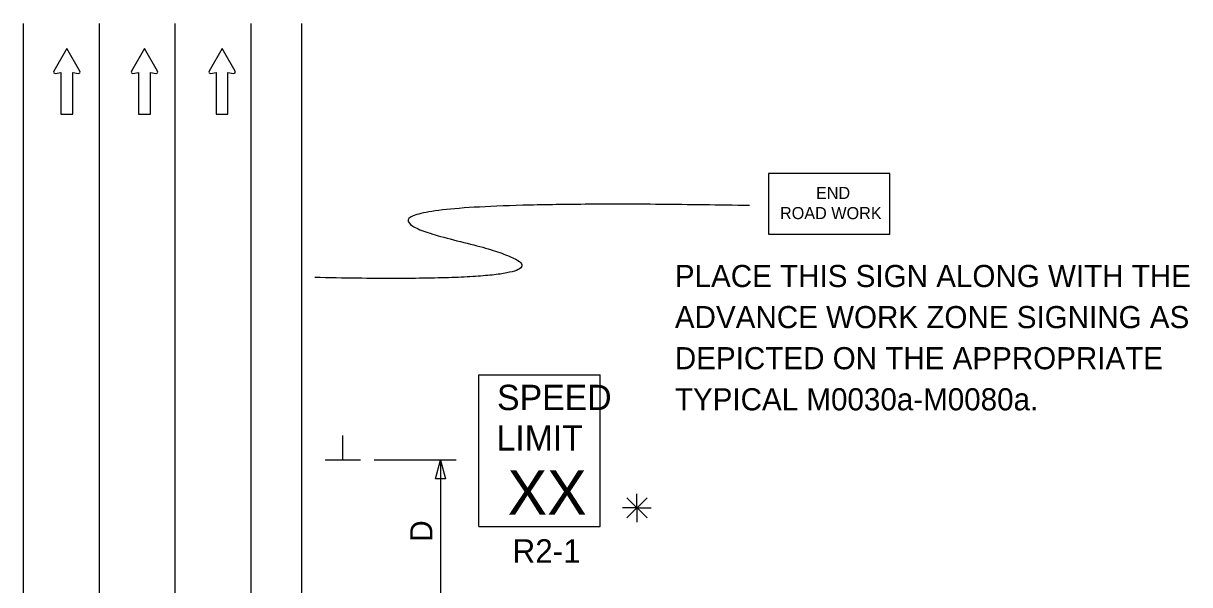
# Model space of a CAD drawing. Extents: x 16744 to 19504, y 5731 to 6974.
# Drawn here: x 17973.5 to 18342.6, y 6713.6 to 6891.2 of the extents above; entities that cross this region are included whole.
import ezdxf

# ---------------------------------------------------------------- set-up
doc = ezdxf.new("R2010")
doc.units = 0
for name, color, linetype in [('ALI_LEGAL_EX', 7, 'Continuous'), ('MT_SCRATCH_LEVEL_E', 7, 'Continuous'), ('PAVT_EDGE_EX', 7, 'Continuous'), ('TRAFFIC_SIGNS_PR', 7, 'Continuous'), ('TYPICAL_TEXT_DIMEN_PR', 7, 'Continuous')]:
    doc.layers.add(name, color=color, linetype=linetype)

msp = doc.modelspace()

# ---------------------------------------------------------------- linework, layer by layer
at = {"layer": 'ALI_LEGAL_EX'}
for p, q in [((17997.5, 6891.16), (17997.5, 6061.98)), ((18021.5, 6891.16), (18021.5, 6061.98)), ((18021.5, 6891.16), (18021.5, 6061.98))]:
    msp.add_line(p, q, dxfattribs=at)
for points in [[(17997.5, 6891.16), (17997.5, 6866.16)], [(18021.5, 6891.16), (18021.5, 6866.16)], [(17997.5, 6791.16), (17997.5, 6766.16)], [(18021.5, 6791.16), (18021.5, 6766.16)]]:
    msp.add_lwpolyline(points, dxfattribs=at)
at = {"layer": 'MT_SCRATCH_LEVEL_E'}
for p, q in [((17987.26, 6883.24), (17983.15, 6876)), ((17987.26, 6883.24), (17983.15, 6876)), ((17991.41, 6876), (17987.26, 6883.24)), ((17991.41, 6876), (17987.26, 6883.24)), ((18011.82, 6883.24), (18007.71, 6876)), ((18011.82, 6883.24), (18007.71, 6876)), ((18015.97, 6876), (18011.82, 6883.24)), ((18015.97, 6876), (18011.82, 6883.24)), ((18036.38, 6883.24), (18032.27, 6876)), ((18036.38, 6883.24), (18032.27, 6876)), ((18040.53, 6876), (18036.38, 6883.24)), ((18040.53, 6876), (18036.38, 6883.24)), ((17983.64, 6875.32), (17985.41, 6875.64)), ((17983.64, 6875.32), (17985.41, 6875.64)), ((17985.41, 6875.64), (17985.41, 6862.38)), ((17985.41, 6875.64), (17985.41, 6862.38)), ((17989.15, 6862.38), (17989.15, 6875.64)), ((17989.15, 6875.64), (17990.93, 6875.32)), ((17989.15, 6862.38), (17989.15, 6875.64)), ((17989.15, 6875.64), (17990.93, 6875.32)), ((18008.19, 6875.32), (18009.97, 6875.64)), ((18008.19, 6875.32), (18009.97, 6875.64)), ((18009.97, 6875.64), (18009.97, 6862.38)), ((18009.97, 6875.64), (18009.97, 6862.38)), ((18013.71, 6862.38), (18013.71, 6875.64)), ((18013.71, 6875.64), (18015.49, 6875.32)), ((18013.71, 6862.38), (18013.71, 6875.64)), ((18013.71, 6875.64), (18015.49, 6875.32)), ((18032.75, 6875.32), (18034.53, 6875.64)), ((18032.75, 6875.32), (18034.53, 6875.64)), ((18034.53, 6875.64), (18034.53, 6862.38)), ((18034.53, 6875.64), (18034.53, 6862.38)), ((18038.27, 6862.38), (18038.27, 6875.64)), ((18038.27, 6875.64), (18040.05, 6875.32)), ((18038.27, 6862.38), (18038.27, 6875.64)), ((18038.27, 6875.64), (18040.05, 6875.32)), ((17985.41, 6862.38), (17989.15, 6862.38)), ((17985.41, 6862.38), (17989.15, 6862.38)), ((18009.97, 6862.38), (18013.71, 6862.38)), ((18009.97, 6862.38), (18013.71, 6862.38)), ((18034.53, 6862.38), (18038.27, 6862.38)), ((18034.53, 6862.38), (18038.27, 6862.38))]:
    msp.add_line(p, q, dxfattribs=at)
for centre, start, end in [((17983.56, 6875.78), 150.4248, 279.9638), ((17983.56, 6875.78), 150.4248, 279.9638), ((17991, 6875.78), 260.0362, 29.7731), ((17991, 6875.78), 260.0362, 29.7731), ((18008.12, 6875.78), 150.4248, 279.9638), ((18008.12, 6875.78), 150.4248, 279.9638), ((18015.56, 6875.78), 260.0362, 29.7731), ((18015.56, 6875.78), 260.0362, 29.7731), ((18032.68, 6875.78), 150.4248, 279.9638), ((18032.68, 6875.78), 150.4248, 279.9638), ((18040.12, 6875.78), 260.0362, 29.7731), ((18040.12, 6875.78), 260.0362, 29.7731)]:
    msp.add_arc(centre, 0.463, start, end, dxfattribs=at)
at = {"layer": 'PAVT_EDGE_EX'}
for p, q in [((17973.5, 6891.16), (17973.5, 6061.98)), ((17973.5, 6891.16), (17973.5, 6061.98)), ((18045.5, 6891.16), (18045.5, 6061.98)), ((18061.5, 6891.16), (18061.5, 6061.98))]:
    msp.add_line(p, q, dxfattribs=at)
at = {"layer": 'TRAFFIC_SIGNS_PR'}
for p, q in [((18117.64, 6779.97), (18156.04, 6779.97)), ((18117.64, 6731.97), (18117.64, 6779.97)), ((18156.04, 6731.97), (18156.04, 6779.97)), ((18117.64, 6731.97), (18156.04, 6731.97))]:
    msp.add_line(p, q, dxfattribs=at)
msp.add_lwpolyline([(18209.35, 6824.48), (18247.75, 6824.48), (18247.75, 6843.68), (18209.35, 6843.68)], close=True, dxfattribs=at)
msp.add_open_spline([(18203.28, 6833.52), (18053.97, 6836.16), (18167.87, 6808.58), (18065.7, 6810.75)], degree=2, dxfattribs=at)
at = {"layer": 'TYPICAL_TEXT_DIMEN_PR'}
for p, q in [((18074.63, 6752.97), (18074.63, 6760.76)), ((18080.25, 6752.97), (18069, 6752.97)), ((18110.5, 6752.97), (18084.5, 6752.97)), ((18103.93, 6747.11), (18105.5, 6752.97)), ((18105.5, 6752.97), (18105.5, 6702.97)), ((18105.5, 6752.97), (18107.07, 6747.11)), ((18105.5, 6747.11), (18103.93, 6747.11)), ((18107.07, 6747.11), (18105.5, 6747.11)), ((18170.87, 6741.1), (18164.49, 6734.73)), ((18164.5, 6741.1), (18170.87, 6734.73)), ((18167.68, 6737.91), (18167.68, 6742.37)), ((18167.68, 6737.91), (18163.15, 6737.91)), ((18167.68, 6737.91), (18170.87, 6737.91)), ((18167.68, 6737.91), (18172.16, 6737.91)), ((18167.68, 6737.91), (18167.68, 6733.41))]:
    msp.add_line(p, q, dxfattribs=at)

# ---------------------------------------------------------------- texts
at = {"layer": 'TRAFFIC_SIGNS_PR'}
for s, height, p in [('END', 3.831, (18224.35, 6835.61)), ('ROAD WORK', 3.831, (18212.96, 6829.22)), ('PLACE THIS SIGN ALONG WITH THE', 7, (18179.69, 6807.74)), ('ADVANCE WORK ZONE SIGNING AS', 7, (18179.69, 6794.74)), ('DEPICTED ON THE APPROPRIATE', 7, (18179.69, 6781.74)), ('SPEED', 8, (18123.41, 6768.83)), ('TYPICAL M0030a-M0080a.', 7, (18179.69, 6768.74)), ('LIMIT', 8, (18123.24, 6756.03)), ('XX', 14.031, (18126.75, 6735.73)), ('R2-1', 7.44, (18128.32, 6720.53))]:
    msp.add_text(s, height=height, dxfattribs=at).set_placement(p)
at = {"layer": 'TYPICAL_TEXT_DIMEN_PR'}
msp.add_text('D', height=7, rotation=90, dxfattribs=at).set_placement((18102.94, 6727.19))

doc.saveas('drawing.dxf')
